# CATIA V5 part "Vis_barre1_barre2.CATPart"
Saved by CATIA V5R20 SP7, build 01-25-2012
Part number: Vis_barre1_barre2
Bounding box of the stored display mesh (mm): x -2.5 to 8.5, y 30.174 to 32.173, z 9.42 to 11.42
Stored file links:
  J:\IFMA\IAO\système avant mef\Vis_barre1_barre2.CATPart
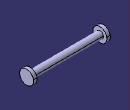
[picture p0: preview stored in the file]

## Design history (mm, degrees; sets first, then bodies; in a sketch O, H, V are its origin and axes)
Body1 (main body)
  Line1: stored without definition
  Point1 "point_Asecond": stored without definition
  Plane1: type Normal, Curve Line1, RefPoint Point1
  Line2 to Line4 "axe_liaison_barre2_barre1": stored without definition
  Line5: stored without definition
  DatumCurve1
  Line6 "barre_5": stored without definition
  Line7 "barre_5": stored without definition
  Line8 "axe_liaison_barre2_barre1": stored without definition
  Sketch1 on Plane1, origin (0, 6.4051, 18.8404), H (-1, 0, 0), V (0, -0.9468, 0.3219)
    point P1 (-8.5, -26.1604)
    line L1 (-8.5, -26.1604) -> (-8.5, -25.1604)
    line L2 (-8.5, -25.1604) -> (-8, -25.1604)
    line L3 (-8, -25.1604) -> (-8, -25.6604)
    line L4 (-8, -25.6604) -> (2, -25.6604)
    line L5 (2, -25.6604) -> (2, -25.1604)
    point P6 (2, -25.1604)
    line L6 (2, -25.1604) -> (2.5, -25.1604)
    line L7 (2.5, -25.1604) -> (2.5, -26.1604)
    point P8 (2.5, -26.1604)
    reference projected line E1 (0, -26.1604) -> (-20, -26.1604) from Line2
    reference projected line E2 (0, -26.1604) -> (-20, -26.1604) from Line3
    reference projected line E3 (0, -26.1604) -> (-20, -26.1604) from Line4
    reference projected line E4 (4, -26.1604) -> (-4, -26.1604) from Line5
    reference projected line E5 (-8, -27.1604) -> (-8, -25.1604) from edge of DatumCurve1
    reference projected line E6 (2, -17.0421) -> (2, -26.1604) from Line6
    reference projected line E7 (2, -17.0421) -> (2, -26.1604) from Line7
    distance L4 E2 = 0.5
    distance L2 E3 = 1
    distance L7 E7 = 0.5
    distance L1 L3 = 0.5
    vertical: L1 V, L3 V, L5 V, L7 V
    horizontal: L2 H, L4 H, L6 H
    coincidence: P6 L2, P1 E1, P8 E4, L3 E5, L5 E6
  Shaft1: profile Sketch1, axis Line8, angle 360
